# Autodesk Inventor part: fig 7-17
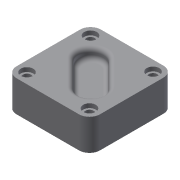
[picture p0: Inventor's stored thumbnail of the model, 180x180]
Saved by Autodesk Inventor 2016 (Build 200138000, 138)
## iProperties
Shininess: 77.0
Angle Display Precision: 2
Document Length Units: 11269
Document Angle Units: 11279
Document Time Units: 11290
Document Mass Units: 11283
Document Length Units Precision: 3
Document Angle Units Precision: 2
Created: 2001-12
Part Number: fig 7-17
Document SubType Name: Modeling
Designer: Renu Muthoo
Density: 1 g/cm^3
Material: Generic
Appearance: Default
Density: 0.0
Volumn: 0.0
Area: 0.0
PropertySet Name: Model Information
Control State: 0
Master: False
Checked Out: False
Author: Renu Muthoo
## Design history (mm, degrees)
sketch "Sketch1"
  geometry: L1 (-20, 20)-(20, 20); L2 (20, 20)-(20, -20.5); L3 (20, -20.5)-(-20, -20.5); L4 (-20, -20.5)-(-20, 20); 1 further point
  constraints: 8 end point, 2 parallel, 1 horizontal, 1 perpendicular, 1 other
  dimensions: "d0" = 40 distance of L1.start L1.end; "d1" = 40.5 distance of L3.end L1.start; "d100" = 20 distance from line of L4 point (0, 0); "d101" = 20 distance from line of L1 point (0, 0)
extrude "Extrusion1" new body sketch "Sketch1" distance "d2" = 15; taper "d3" = 0 deg
workplane "Work Plane1"
workplane "Work Plane2"
workplane "Work Plane3"
fillet "Fillet1" dims "d32" = 5
hole "Hole3" diameter "d66" = 4; stored, may be unused: countersink angle "d70" = 90 deg, drill point angle "d72" = 118 deg; dims "d64" = 10, "d65" = 10, "d67" = 6, "d68" = 6, "d69" = 2, "d71" = 8
hole "Hole4" diameter "d75" = 4; stored, may be unused: countersink angle "d79" = 90 deg, drill point angle "d81" = 118 deg; dims "d73" = 10, "d74" = 10, "d76" = 6, "d77" = 6, "d78" = 2, "d80" = 8
hole "Hole5" diameter "d84" = 4; stored, may be unused: countersink angle "d88" = 90 deg, drill point angle "d90" = 118 deg; dims "d82" = 10, "d83" = 10, "d85" = 6, "d86" = 6, "d87" = 2, "d89" = 8
hole "Hole6" diameter "d93" = 4; stored, may be unused: countersink angle "d97" = 90 deg, drill point angle "d99" = 118 deg; dims "d91" = 10, "d92" = 10, "d94" = 6, "d95" = 6, "d96" = 2, "d98" = 8
fillet "Fillet2" dims "d61" = 2
body "Solid1"
sketch "Sketch8"
  geometry: L1 (-9.844, 1.64)-(1.983, -10.187); L2 (10.469, -1.701)-(-1.358, 10.126); A1 r 6 centre (-5.601, 5.883) between (-1.358, 10.126) and (-9.844, 1.64); A2 r 6 centre (6.226, -5.944) between (1.983, -10.187) and (10.469, -1.701)
  constraints: 4 end point, 4 point on circle, 4 tangent, 2 centre point, 1 parallel
  dimensions: "d29" = 6 radius of A2
extrude "Extrusion2" cut sketch "Sketch8" distance "d30" = 5; taper "d31" = 0 deg
